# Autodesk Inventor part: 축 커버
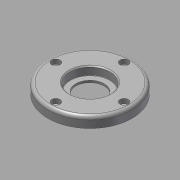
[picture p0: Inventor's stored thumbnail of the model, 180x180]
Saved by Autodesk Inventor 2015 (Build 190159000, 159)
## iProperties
Created: 2015-10
Part Number: 축 커버
Document SubType Name: Modeling
Designer: mdu
Density: 7.86 g/cm^3
Material: 강철, 연강
Appearance: Steel
Mass: 322.464 g
Surface Area: 133.703 cm^2
Volume: 41.026 cm^3
Author: mdu
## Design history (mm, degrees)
sketch "스케치1"
  geometry: C1 r 40 at (0, 0) reference; C2 r 26 at (0, 0) reference; 1 further point
  node "참조1"
  node "참조2"
extrude "돌출1" new body sketch "스케치1" distance "d0" = 10; taper "d1" = 0 deg
extrude "돌출2" join sketch "스케치1" distance "d2" = 3; taper "d3" = 0 deg
hole "구멍1" diameter "d6" = 27; stored, may be unused: countersink angle "d10" = 90 deg, drill point angle "d12" = 118 deg; dims "d4" = 10, "d5" = 10, "d7" = 6, "d8" = 38, "d9" = 8, "d11" = 8
sketch "스케치2"
  geometry: C1 r 20 at (0, 0); 1 further point
  constraints: 1 centre point, 1 coincident
  dimensions: "d13" = 40 diameter of C1
extrude "돌출3" cut sketch "스케치2" distance "d14" = 3; taper "d15" = 0 deg
sketch "스케치3"
  geometry: C1 r 1.621 at (0, 32.5) reference; 1 further point
hole "구멍2" sketch "스케치3" at (0, 32.5) diameter "d16" = 4.5; stored, may be unused: countersink angle "d20" = 90 deg, drill point angle "d22" = 118 deg; dims "d17" = 6, "d18" = 8, "d19" = 4.4, "d21" = 8
fillet "모깎기1" dims "d26" = 3, "d27" = 0.3
chamfer "모따기1" distance "d28" = 1; stored, may be unused: second distance "d29" = 2, angle "d30" = 45 deg
node "솔리드1"
pattern_circular "원형 패턴1" dims angle "d24" = 360 deg
node "참조3"
